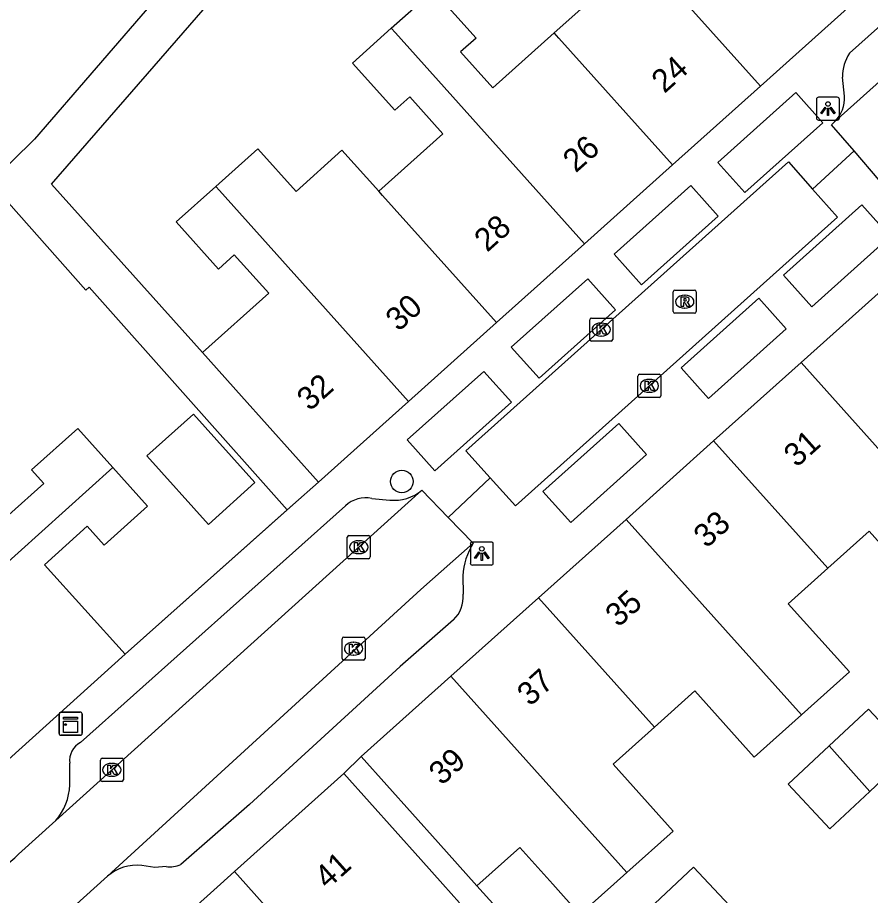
# Model space of a CAD drawing. Extents: x 158352 to 159489, y 383828 to 384597.
# Drawn here: x 159153.3 to 159190.27, y 384249.51 to 384287.56 of the extents above; entities that cross this region are included whole.
import ezdxf

# ---------------------------------------------------------------- set-up
doc = ezdxf.new("R2010")
doc.units = 0
for name, color, linetype in [('IMGEO_Boom', 7, 'Continuous'), ('IMGEO_Kast', 7, 'Continuous'), ('IMGEO_Kolk', 7, 'Continuous'), ('IMGEO_Lichtpunt', 7, 'Continuous'), ('IMGEO_Muur', 7, 'Continuous'), ('IMGEO_Pand', 7, 'Continuous'), ('IMGEO_Pand_nummerreeks', 7, 'Continuous'), ('IMGEO_Rijbaan_lokaal_open', 7, 'Continuous'), ('IMGEO_Rioolput', 7, 'Continuous'), ('IMGEO_Voetpad_open', 7, 'Continuous')]:
    doc.layers.add(name, color=color, linetype=linetype)

msp = doc.modelspace()

# ---------------------------------------------------------------- linework, layer by layer
at = {"layer": 'IMGEO_Boom'}
msp.add_circle((159169.953, 384267.452), 0.489, dxfattribs=at)
at = {"layer": 'IMGEO_Kast'}
for p, q in [((159155.173, 384257.455), (159156.014, 384257.455)), ((159156.014, 384257.455), (159155.173, 384257.455)), ((159155.098, 384256.53), (159155.098, 384257.371)), ((159155.098, 384257.371), (159155.098, 384256.53)), ((159156.098, 384257.38), (159156.098, 384256.539)), ((159156.098, 384256.539), (159156.098, 384257.38)), ((159156.023, 384256.455), (159155.182, 384256.455)), ((159155.182, 384256.455), (159156.023, 384256.455))]:
    msp.add_line(p, q, dxfattribs=at)
for points in [[(159155.293, 384257.245), (159155.893, 384257.245), (159155.893, 384257.16), (159155.293, 384257.16), (159155.293, 384257.245)], [(159155.293, 384257.07), (159155.893, 384257.07), (159155.893, 384256.581), (159155.293, 384256.581), (159155.293, 384257.07)]]:
    msp.add_lwpolyline(points, dxfattribs=at)
msp.add_circle((159155.377, 384256.919), 0.0377, dxfattribs=at)
for centre, start, end in [((159155.176, 384257.377), 92.4484, 184.2845), ((159155.176, 384257.377), 92.4484, 184.2845), ((159156.02, 384257.377), 2.4484, 94.2845), ((159156.02, 384257.377), 2.4484, 94.2845), ((159155.176, 384256.533), 182.4484, 274.2845), ((159155.176, 384256.533), 182.4484, 274.2845), ((159156.02, 384256.533), 272.4484, 4.2845), ((159156.02, 384256.533), 272.4484, 4.2845)]:
    msp.add_arc(centre, 0.0779, start, end, dxfattribs=at)
at = {"layer": 'IMGEO_Kolk'}
for p, q in [((159178.099, 384273.613), (159178.099, 384274.465)), ((159178.174, 384274.539), (159179.026, 384274.539)), ((159178.587, 384274.319), (159178.612, 384274.319)), ((159179.1, 384274.465), (159179.1, 384273.613)), ((159179.026, 384273.539), (159178.174, 384273.539)), ((159178.61, 384273.759), (159178.585, 384273.759)), ((159180.184, 384271.173), (159180.184, 384272.025)), ((159180.259, 384272.099), (159181.111, 384272.099)), ((159181.185, 384272.025), (159181.185, 384271.173)), ((159180.672, 384271.879), (159180.697, 384271.879)), ((159180.695, 384271.319), (159180.67, 384271.319)), ((159181.111, 384271.099), (159180.259, 384271.099)), ((159167.663, 384265.109), (159168.515, 384265.109)), ((159167.588, 384264.183), (159167.588, 384265.035)), ((159168.076, 384264.889), (159168.101, 384264.889)), ((159168.589, 384265.035), (159168.589, 384264.183)), ((159168.099, 384264.329), (159168.074, 384264.329)), ((159168.515, 384264.109), (159167.663, 384264.109)), ((159167.365, 384259.784), (159167.365, 384260.636)), ((159167.44, 384260.71), (159168.292, 384260.71)), ((159167.853, 384260.49), (159167.878, 384260.49)), ((159168.366, 384260.636), (159168.366, 384259.784)), ((159167.876, 384259.93), (159167.851, 384259.93)), ((159168.292, 384259.71), (159167.44, 384259.71)), ((159156.888, 384254.53), (159156.888, 384255.382)), ((159156.963, 384255.456), (159157.815, 384255.456)), ((159157.376, 384255.236), (159157.401, 384255.236)), ((159157.889, 384255.382), (159157.889, 384254.53)), ((159157.815, 384254.456), (159156.963, 384254.456)), ((159157.399, 384254.676), (159157.374, 384254.676))]:
    msp.add_line(p, q, dxfattribs=at)
for points in [[(159178.099, 384273.613), (159178.099, 384274.465)], [(159178.174, 384274.539), (159179.026, 384274.539)], [(159178.42, 384274.239), (159178.543, 384274.239), (159178.543, 384274.088), (159178.673, 384274.239), (159178.837, 384274.239), (159178.691, 384274.088), (159178.844, 384273.839), (159178.692, 384273.839), (159178.607, 384274.003), (159178.543, 384273.936), (159178.543, 384273.839), (159178.42, 384273.839), (159178.42, 384274.239)], [(159179.1, 384274.465), (159179.1, 384273.613)], [(159179.026, 384273.539), (159178.174, 384273.539)], [(159180.184, 384271.173), (159180.184, 384272.025)], [(159180.259, 384272.099), (159181.111, 384272.099)], [(159181.185, 384272.025), (159181.185, 384271.173)], [(159180.505, 384271.799), (159180.628, 384271.799), (159180.628, 384271.648), (159180.758, 384271.799), (159180.922, 384271.799), (159180.776, 384271.648), (159180.929, 384271.399), (159180.777, 384271.399), (159180.692, 384271.563), (159180.628, 384271.496), (159180.628, 384271.399), (159180.505, 384271.399), (159180.505, 384271.799)], [(159181.111, 384271.099), (159180.259, 384271.099)], [(159167.663, 384265.109), (159168.515, 384265.109)], [(159167.588, 384264.183), (159167.588, 384265.035)], [(159167.909, 384264.809), (159168.032, 384264.809), (159168.032, 384264.658), (159168.162, 384264.809), (159168.326, 384264.809), (159168.18, 384264.658), (159168.333, 384264.409), (159168.181, 384264.409), (159168.096, 384264.573), (159168.032, 384264.506), (159168.032, 384264.409), (159167.909, 384264.409), (159167.909, 384264.809)], [(159168.589, 384265.035), (159168.589, 384264.183)], [(159168.515, 384264.109), (159167.663, 384264.109)], [(159167.365, 384259.784), (159167.365, 384260.636)], [(159167.44, 384260.71), (159168.292, 384260.71)], [(159168.366, 384260.636), (159168.366, 384259.784)], [(159167.686, 384260.41), (159167.809, 384260.41), (159167.809, 384260.259), (159167.939, 384260.41), (159168.103, 384260.41), (159167.957, 384260.259), (159168.11, 384260.01), (159167.958, 384260.01), (159167.873, 384260.174), (159167.809, 384260.107), (159167.809, 384260.01), (159167.686, 384260.01), (159167.686, 384260.41)], [(159168.292, 384259.71), (159167.44, 384259.71)], [(159156.888, 384254.53), (159156.888, 384255.382)], [(159156.963, 384255.456), (159157.815, 384255.456)], [(159157.889, 384255.382), (159157.889, 384254.53)], [(159157.209, 384255.156), (159157.332, 384255.156), (159157.332, 384255.005), (159157.462, 384255.156), (159157.626, 384255.156), (159157.48, 384255.005), (159157.633, 384254.756), (159157.481, 384254.756), (159157.396, 384254.92), (159157.332, 384254.853), (159157.332, 384254.756), (159157.209, 384254.756), (159157.209, 384255.156)], [(159157.815, 384254.456), (159156.963, 384254.456)]]:
    msp.add_lwpolyline(points, dxfattribs=at)
for centre, start, end in [((159178.176, 384274.463), 91.552, 178.448), ((159178.176, 384274.463), 91.552, 178.448), ((159179.024, 384274.463), 1.552, 88.448), ((159179.024, 384274.463), 1.552, 88.448), ((159178.176, 384273.615), 181.552, 268.448), ((159178.176, 384273.615), 181.552, 268.448), ((159179.024, 384273.615), 271.552, 358.448), ((159179.024, 384273.615), 271.552, 358.448), ((159180.261, 384272.023), 91.552, 178.448), ((159180.261, 384272.023), 91.552, 178.448), ((159181.109, 384272.023), 1.552, 88.448), ((159181.109, 384272.023), 1.552, 88.448), ((159180.261, 384271.175), 181.552, 268.448), ((159180.261, 384271.175), 181.552, 268.448), ((159181.109, 384271.175), 271.552, 358.448), ((159181.109, 384271.175), 271.552, 358.448), ((159167.665, 384265.033), 91.552, 178.448), ((159167.665, 384265.033), 91.552, 178.448), ((159168.513, 384265.033), 1.552, 88.448), ((159168.513, 384265.033), 1.552, 88.448), ((159167.665, 384264.185), 181.552, 268.448), ((159167.665, 384264.185), 181.552, 268.448), ((159168.513, 384264.185), 271.552, 358.448), ((159168.513, 384264.185), 271.552, 358.448), ((159167.442, 384260.634), 91.552, 178.448), ((159167.442, 384260.634), 91.552, 178.448), ((159168.29, 384260.634), 1.552, 88.448), ((159168.29, 384260.634), 1.552, 88.448), ((159167.442, 384259.786), 181.552, 268.448), ((159167.442, 384259.786), 181.552, 268.448), ((159168.29, 384259.786), 271.552, 358.448), ((159168.29, 384259.786), 271.552, 358.448), ((159156.965, 384255.38), 91.552, 178.448), ((159156.965, 384255.38), 91.552, 178.448), ((159157.813, 384255.38), 1.552, 88.448), ((159157.813, 384255.38), 1.552, 88.448), ((159156.965, 384254.532), 181.552, 268.448), ((159156.965, 384254.532), 181.552, 268.448), ((159157.813, 384254.532), 271.552, 358.448), ((159157.813, 384254.532), 271.552, 358.448)]:
    msp.add_arc(centre, 0.0765, start, end, dxfattribs=at)
for centre, major_axis, ratio, start_param, end_param in [((159178.586, 384274.039), (-0.387, 0.002), 0.722429, 4.712389, 7.853982), ((159178.611, 384274.039), (-0.39, 0.002), 0.717154, 1.570796, 4.712389), ((159180.671, 384271.599), (-0.387, 0.002), 0.722429, 4.712389, 7.853982), ((159180.696, 384271.599), (-0.39, 0.002), 0.717154, 1.570796, 4.712389), ((159168.075, 384264.609), (-0.387, 0.002), 0.722429, 4.712389, 7.853982), ((159168.1, 384264.609), (-0.39, 0.002), 0.717154, 1.570796, 4.712389), ((159167.852, 384260.21), (-0.387, 0.002), 0.722429, 4.712389, 7.853982), ((159167.877, 384260.21), (-0.39, 0.002), 0.717154, 1.570796, 4.712389), ((159157.375, 384254.956), (-0.387, 0.002), 0.722429, 4.712389, 7.853982), ((159157.4, 384254.956), (-0.39, 0.002), 0.717154, 1.570796, 4.712389)]:
    msp.add_ellipse(centre, major_axis=major_axis, ratio=ratio, start_param=start_param, end_param=end_param, dxfattribs=at)
at = {"layer": 'IMGEO_Lichtpunt'}
for p, q in [((159188.83, 384284.111), (159188.022, 384284.111)), ((159188.83, 384284.111), (159188.022, 384284.111)), ((159187.928, 384284.016), (159187.928, 384283.209)), ((159187.928, 384284.016), (159187.928, 384283.209)), ((159188.924, 384283.209), (159188.924, 384284.016)), ((159188.924, 384283.209), (159188.924, 384284.016)), ((159188.022, 384283.115), (159188.83, 384283.115)), ((159188.022, 384283.115), (159188.83, 384283.115)), ((159172.925, 384264.736), (159172.925, 384263.929)), ((159172.925, 384264.736), (159172.925, 384263.929)), ((159173.827, 384264.831), (159173.019, 384264.831)), ((159173.827, 384264.831), (159173.019, 384264.831)), ((159173.921, 384263.929), (159173.921, 384264.736)), ((159173.921, 384263.929), (159173.921, 384264.736)), ((159173.019, 384263.835), (159173.827, 384263.835)), ((159173.019, 384263.835), (159173.827, 384263.835))]:
    msp.add_line(p, q, dxfattribs=at)
for points in [[(159188.302, 384283.68), (159188.341, 384283.652), (159188.153, 384283.39), (159188.115, 384283.417), (159188.302, 384283.68)], [(159188.404, 384283.632), (159188.451, 384283.632), (159188.451, 384283.31), (159188.404, 384283.31), (159188.404, 384283.632)], [(159188.514, 384283.652), (159188.552, 384283.679), (159188.739, 384283.417), (159188.7, 384283.389), (159188.514, 384283.652)], [(159173.299, 384264.4), (159173.338, 384264.372), (159173.15, 384264.11), (159173.112, 384264.137), (159173.299, 384264.4)], [(159173.401, 384264.352), (159173.448, 384264.352), (159173.448, 384264.03), (159173.401, 384264.03), (159173.401, 384264.352)], [(159173.511, 384264.372), (159173.549, 384264.399), (159173.736, 384264.137), (159173.697, 384264.109), (159173.511, 384264.372)]]:
    msp.add_lwpolyline(points, dxfattribs=at)
for centre in [(159188.427, 384283.814), (159173.424, 384264.534)]:
    msp.add_circle(centre, 0.0994, dxfattribs=at)
for centre, start, end in [((159188.022, 384284.016), 90, 180), ((159188.022, 384284.016), 90, 180), ((159188.83, 384284.016), 0, 90), ((159188.83, 384284.016), 0, 90), ((159188.022, 384283.209), 180, 270), ((159188.022, 384283.209), 180, 270), ((159188.83, 384283.209), 270, 0), ((159188.83, 384283.209), 270, 360), ((159173.019, 384264.736), 90, 180), ((159173.019, 384264.736), 90, 180), ((159173.827, 384264.736), 0, 90), ((159173.827, 384264.736), 0, 90), ((159173.019, 384263.929), 180, 270), ((159173.019, 384263.929), 180, 270), ((159173.827, 384263.929), 270, 0), ((159173.827, 384263.929), 270, 360)]:
    msp.add_arc(centre, 0.0946, start, end, dxfattribs=at)
at = {"layer": 'IMGEO_Muur'}
msp.add_lwpolyline([(159157.957, 384259.976), (159165.238, 384266.444)], dxfattribs=at)
at = {"layer": 'IMGEO_Pand'}
for points in [[(159176.554, 384286.898), (159179.271, 384289.332), (159177.901, 384290.861), (159177.275, 384290.3), (159175.368, 384292.429), (159177.089, 384293.971)], [(159177.089, 384293.971), (159177.343, 384293.688), (159185.498, 384284.588)], [(159169.5, 384287.098), (159171.326, 384288.734), (159173.171, 384286.674), (159172.499, 384286.072), (159173.894, 384284.515), (159176.554, 384286.898)], [(159189.399, 384288.084), (159185.498, 384284.588)], [(159168.958, 384280.032), (159171.737, 384282.523), (159170.304, 384284.123), (159169.654, 384283.541), (159167.817, 384285.59), (159169.5, 384287.098)], [(159169.5, 384287.098), (159169.683, 384286.894), (159177.872, 384277.756)], [(159181.684, 384281.172), (159176.763, 384286.664), (159176.554, 384286.898)], [(159185.498, 384284.588), (159181.684, 384281.172)], [(159161.896, 384280.241), (159163.717, 384281.872), (159165.37, 384280.027), (159167.362, 384281.813), (159168.958, 384280.032)], [(159181.684, 384281.172), (159177.872, 384277.756)], [(159161.312, 384273.043), (159164.185, 384275.617), (159162.694, 384277.281), (159162.005, 384276.663), (159160.178, 384278.702), (159161.896, 384280.241)], [(159170.246, 384270.923), (159162.054, 384280.065), (159161.896, 384280.241)], [(159174.059, 384274.34), (159169.122, 384279.849), (159168.958, 384280.032)], [(159177.872, 384277.756), (159174.059, 384274.34)], [(159187.267, 384272.613), (159191.152, 384276.093)], [(159174.059, 384274.34), (159170.246, 384270.923)], [(159166.344, 384267.427), (159163.008, 384271.151), (159161.312, 384273.043)], [(159183.472, 384269.212), (159187.267, 384272.613)], [(159194.798, 384264.208), (159187.267, 384272.613)], [(159170.246, 384270.923), (159166.344, 384267.427)], [(159158.906, 384268.569), (159161.569, 384265.597), (159163.589, 384267.406), (159160.926, 384270.379), (159158.906, 384268.569)], [(159149.739, 384269.542), (159152.922, 384266.009), (159154.432, 384267.37), (159153.906, 384267.954), (159155.907, 384269.757), (159157.429, 384268.067)], [(159179.676, 384265.811), (159183.472, 384269.212)], [(159183.472, 384269.212), (159188.419, 384263.692)], [(159148.18, 384259.732), (159157.429, 384268.067)], [(159157.429, 384268.067), (159158.938, 384266.391), (159157.058, 384264.697), (159156.321, 384265.514), (159154.47, 384263.847), (159157.957, 384259.976)], [(159175.881, 384262.411), (159179.676, 384265.811)], [(159179.676, 384265.811), (159187.273, 384257.334)], [(159188.419, 384263.692), (159190.212, 384265.298), (159192.796, 384262.414), (159194.798, 384264.208)], [(159187.273, 384257.334), (159189.355, 384259.199), (159186.705, 384262.156), (159188.419, 384263.692)], [(159172.085, 384259.01), (159175.881, 384262.411)], [(159180.901, 384256.809), (159175.881, 384262.411)], [(159157.957, 384259.976), (159152.439, 384255.004)], [(159168.2, 384255.529), (159172.085, 384259.01)], [(159172.085, 384259.01), (159179.709, 384250.503)], [(159180.901, 384256.809), (159182.652, 384258.378), (159185.228, 384255.502), (159187.273, 384257.334)], [(159188.478, 384255.99), (159190.187, 384257.592), (159191.993, 384255.666), (159190.241, 384254.023)], [(159179.709, 384250.503), (159181.72, 384252.303), (159179.115, 384255.209), (159180.901, 384256.809)], [(159188.478, 384255.99), (159186.707, 384254.33), (159188.513, 384252.403), (159190.241, 384254.023)], [(159190.241, 384254.023), (159188.478, 384255.99)], [(159173.212, 384249.934), (159171.536, 384251.805), (159168.2, 384255.529)], [(159162.702, 384250.546), (159167.448, 384254.795)], [(159167.448, 384254.795), (159170.784, 384251.07), (159171.735, 384250), (159172.449, 384249.196)], [(159173.212, 384249.934), (159175.067, 384251.594), (159176.495, 384250), (159177.675, 384248.682), (159179.147, 384250), (159179.709, 384250.503)], [(159180.915, 384249.157), (159182.604, 384250.74), (159184.379, 384248.848), (159182.648, 384247.225)], [(159159.373, 384247.566), (159162.092, 384250), (159162.702, 384250.546)], [(159162.702, 384250.546), (159163.19, 384250), (159167.702, 384244.952)]]:
    msp.add_lwpolyline(points, dxfattribs=at)
at = {"layer": 'IMGEO_Rijbaan_lokaal_open'}
for points in [[(159188.728, 384283.052), (159204.28, 384296.997)], [(159189.555, 384281.784), (159188.576, 384282.918), (159188.728, 384283.052)], [(159190.807, 384280.663), (159190.645, 384280.52), (159189.555, 384281.784)], [(159173.783, 384267.611), (159172.731, 384268.781), (159186.714, 384281.303), (159187.751, 384280.129)], [(159187.751, 384280.129), (159188.834, 384278.904), (159174.877, 384266.394), (159173.783, 384267.611)], [(159170.825, 384267.076), (159154.952, 384252.756)], [(159170.825, 384267.076), (159171.966, 384265.9)], [(159171.966, 384265.9), (159173.053, 384264.779)], [(159173.053, 384264.779), (159170.776, 384262.774), (159157.205, 384250.343)], [(159153.342, 384251.303), (159154.952, 384252.756)], [(159157.205, 384250.343), (159153.327, 384246.849), (159144.971, 384239.34)]]:
    msp.add_lwpolyline(points, dxfattribs=at)
msp.add_arc((159150.301, 384254.266), 4.245, 266.9999, 315.7467, dxfattribs=at)
at = {"layer": 'IMGEO_Rioolput'}
for p, q in [((159181.792, 384275.748), (159182.644, 384275.748)), ((159181.717, 384274.822), (159181.717, 384275.674)), ((159182.205, 384275.528), (159182.23, 384275.528)), ((159182.718, 384275.674), (159182.718, 384274.822)), ((159182.228, 384274.968), (159182.203, 384274.968)), ((159182.644, 384274.748), (159181.792, 384274.748))]:
    msp.add_line(p, q, dxfattribs=at)
for points in [[(159181.792, 384275.748), (159182.644, 384275.748)], [(159181.717, 384274.822), (159181.717, 384275.674)], [(159182.306, 384275.446), (159182.054, 384275.448), (159182.054, 384275.048)], [(159182.232, 384275.367), (159182.178, 384275.367), (159182.178, 384275.286)], [(159182.718, 384275.674), (159182.718, 384274.822)], [(159182.054, 384275.048), (159182.178, 384275.048), (159182.178, 384275.21), (159182.189, 384275.21)], [(159182.178, 384275.286), (159182.23, 384275.286)], [(159182.236, 384275.181), (159182.307, 384275.048), (159182.447, 384275.048), (159182.382, 384275.174)], [(159182.644, 384274.748), (159181.792, 384274.748)]]:
    msp.add_lwpolyline(points, dxfattribs=at)
for centre, radius, start, end in [((159181.794, 384275.672), 0.0765, 91.552, 178.448), ((159181.794, 384275.672), 0.0765, 91.552, 178.448), ((159182.642, 384275.672), 0.0765, 1.552, 88.448), ((159182.642, 384275.672), 0.0765, 1.552, 88.448), ((159182.238, 384275.271), 0.0964, 77.0061, 93.1865), ((159182.252, 384275.328), 0.0378, 276.6634, 79.6772), ((159182.305, 384275.336), 0.109, 350.3612, 89.416), ((159182.188, 384275.157), 0.0533, 26.0293, 88.6989), ((159182.214, 384275.475), 0.19, 274.7715, 282.9687), ((159182.303, 384275.336), 0.112, 277.5842, 350.9817), ((159182.287, 384275.121), 0.108, 29.5134, 73.7905), ((159181.794, 384274.824), 0.0765, 181.552, 268.448), ((159181.794, 384274.824), 0.0765, 181.552, 268.448), ((159182.642, 384274.824), 0.0765, 271.552, 358.448), ((159182.642, 384274.824), 0.0765, 271.552, 358.448)]:
    msp.add_arc(centre, radius, start, end, dxfattribs=at)
for centre, major_axis, ratio, start_param, end_param in [((159182.204, 384275.248), (-0.387, 0.002), 0.722429, 4.712389, 7.853982), ((159182.229, 384275.248), (-0.39, 0.002), 0.717154, 1.570796, 4.712389)]:
    msp.add_ellipse(centre, major_axis=major_axis, ratio=ratio, start_param=start_param, end_param=end_param, dxfattribs=at)
at = {"layer": 'IMGEO_Voetpad_open'}
for points in [[(159132.249, 384287.558), (159149.628, 384303.199), (159157.36, 384296.152), (159162.054, 384291.576), (159154.04, 384282.284), (159152.116, 384280.413), (159156.255, 384275.749), (159156.404, 384275.881), (159164.986, 384266.22)], [(159161.312, 384273.043), (159154.77, 384280.345), (159165.213, 384292.356), (159173.245, 384302.352), (159180.81, 384297.099), (159184.067, 384293.692)], [(159189.361, 384286.012), (159198.802, 384294.468), (159201.05, 384296.506)], [(159189.142, 384284.158), (159189.054, 384284.984)], [(159183.651, 384281.279), (159187.032, 384284.307), (159188.2, 384283.003), (159184.819, 384279.975), (159183.651, 384281.279)], [(159187.751, 384280.129), (159189.555, 384281.784)], [(159179.158, 384277.304), (159182.479, 384280.279), (159183.672, 384278.947), (159180.35, 384275.972), (159179.158, 384277.304)], [(159186.501, 384276.399), (159189.896, 384279.439), (159191.124, 384278.068), (159187.729, 384275.028), (159186.501, 384276.399)], [(159174.699, 384273.27), (159178.018, 384276.242), (159179.222, 384274.899), (159175.903, 384271.927), (159174.699, 384273.27)], [(159182.057, 384272.385), (159185.424, 384275.401), (159186.616, 384274.07), (159183.249, 384271.054), (159182.057, 384272.385)], [(159170.194, 384269.261), (159173.506, 384272.228), (159174.705, 384270.889), (159171.392, 384267.923), (159170.194, 384269.261)], [(159196.077, 384270.597), (159208.021, 384256.898), (159208.473, 384256.408), (159208.892, 384255.953), (159202.639, 384248.958), (159202.328, 384249.236), (159187.896, 384233.696), (159173.212, 384249.934)], [(159176.069, 384267.019), (159179.362, 384269.968), (159180.567, 384268.622), (159177.275, 384265.673), (159176.069, 384267.019)], [(159164.986, 384266.22), (159165.238, 384266.444), (159166.344, 384267.427)], [(159171.966, 384265.9), (159173.783, 384267.611)], [(159168.657, 384266.716), (159169.431, 384266.651)], [(159156.03, 384256.145), (159167.513, 384266.4)], [(159164.986, 384266.22), (159157.957, 384259.976)], [(159172.601, 384263.371), (159172.614, 384262.564)], [(159172.2, 384261.453), (159169.889, 384259.436), (159163.347, 384253.458), (159160.376, 384250.851)], [(159155.57, 384254.304), (159155.559, 384255.244)], [(159167.448, 384254.795), (159168.2, 384255.529)], [(159159.735, 384250.763), (159159.247, 384250.725), (159158.681, 384250.813)]]:
    msp.add_lwpolyline(points, dxfattribs=at)
for centre, radius, start, end in [((159190.895, 384284.994), 1.841, 146.4325, 180.3123), ((159187.652, 384284.085), 1.492, 316.1602, 2.7959), ((159169.637, 384268.472), 1.833, 263.5328, 310.3778), ((159168.391, 384265.45), 1.294, 78.1435, 132.7393), ((159175.43, 384263.239), 2.832, 147.0693, 177.3351), ((159171.176, 384262.467), 1.441, 315.2711, 3.8544), ((159156.453, 384255.35), 0.9, 118.0311, 186.7721), ((159152.984, 384254.439), 2.589, 319.4613, 357.0125), ((159158.462, 384248.948), 1.878, 83.3006, 132.0253), ((159159.908, 384251.884), 1.134, 261.2414, 294.3926)]:
    msp.add_arc(centre, radius, start, end, dxfattribs=at)

# ---------------------------------------------------------------- texts
at = {"layer": 'IMGEO_Pand_nummerreeks'}
for s, rotation, p in [('24', 41.86, (159181.338, 384284.246)), ('26', 41.86, (159177.496, 384280.803)), ('28', 41.86, (159173.655, 384277.362)), ('30', 41.8603, (159169.813, 384273.919)), ('32', 41.86, (159165.966, 384270.472)), ('31', 41.859, (159187.071, 384268.033)), ('33', 41.859, (159183.162, 384264.531)), ('35', 41.859, (159179.337, 384261.103)), ('37', 41.859, (159175.511, 384257.676)), ('39', 41.859, (159171.686, 384254.249)), ('41', 41.8375, (159166.732, 384249.752))]:
    msp.add_text(s, height=1, rotation=rotation, dxfattribs=at).set_placement(p)

doc.saveas('drawing.dxf')
